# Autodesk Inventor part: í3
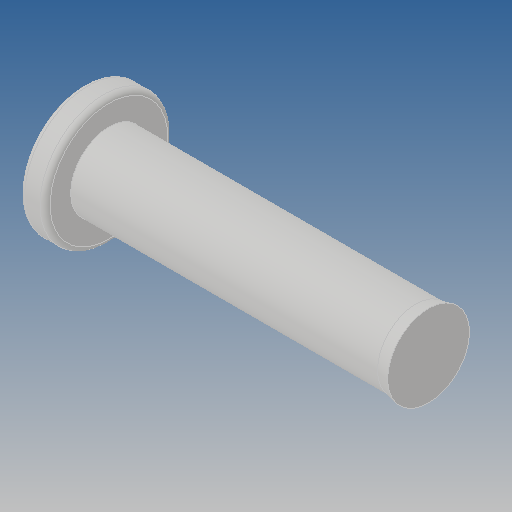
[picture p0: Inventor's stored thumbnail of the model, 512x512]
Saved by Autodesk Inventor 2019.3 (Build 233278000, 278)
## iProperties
Created: 2017-12
Part Number: í3
Material: Ogólny
Document SubType Name: Modeling
Designer: Admin
Density: 1 g/cm^3
Appearance: Domyślna
Author: Admin
Revision Number: ÈÎºÎ
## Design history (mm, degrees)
feature "Ðý×ª1"
node "Bryła1"
